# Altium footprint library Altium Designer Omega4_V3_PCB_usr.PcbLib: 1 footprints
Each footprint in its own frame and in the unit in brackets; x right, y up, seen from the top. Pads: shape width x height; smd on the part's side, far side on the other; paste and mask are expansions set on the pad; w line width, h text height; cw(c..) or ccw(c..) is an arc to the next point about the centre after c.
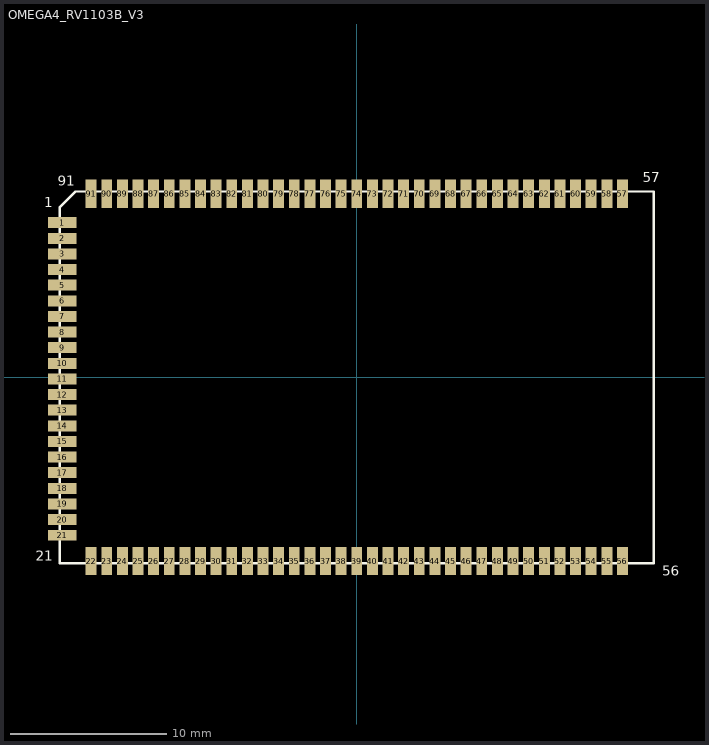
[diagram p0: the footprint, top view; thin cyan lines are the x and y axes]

## OMEGA4_RV1103B_V3 [mm]
pads (91):
  rect 1.8x0.7 smd: 1(-18.85,9.9) 2(-18.85,8.9) 3(-18.85,7.9) 4(-18.85,6.9) 5(-18.85,5.9) 6(-18.85,4.9) 7(-18.85,3.9) 8(-18.85,2.9) 9(-18.85,1.9) 10(-18.85,0.9) 11(-18.85,-0.1) 12(-18.85,-1.1) 13(-18.85,-2.1) 14(-18.85,-3.1) 15(-18.85,-4.1) 16(-18.85,-5.1) 17(-18.85,-6.1) 18(-18.85,-7.1) 19(-18.85,-8.1) 20(-18.85,-9.1) 21(-18.85,-10.1)
  rect 0.7x1.8 smd: 22(-17,-11.75) 23(-16,-11.75) 24(-15,-11.75) 25(-14,-11.75) 26(-13,-11.75) 27(-12,-11.75) 28(-11,-11.75) 29(-10,-11.75) 30(-9,-11.75) 31(-8,-11.75) 32(-7,-11.75) 33(-6,-11.75) 34(-5,-11.75) 35(-4,-11.75) 36(-3,-11.75) 37(-2,-11.75) 38(-1,-11.75) 39(0,-11.75) 40(1,-11.75) 41(2,-11.75) 42(3,-11.75) 43(4,-11.75) 44(5,-11.75) 45(6,-11.75) 46(7,-11.75) 47(8,-11.75) 48(9,-11.75) 49(10,-11.75) 50(11,-11.75) 51(12,-11.75) 52(13,-11.75) 53(14,-11.75) 54(15,-11.75) 55(16,-11.75) 56(17,-11.75) 57(17,11.75) 58(16,11.75) 59(15,11.75) 60(14,11.75) 61(13,11.75) 62(12,11.75) 63(11,11.75) 64(10,11.75) 65(9,11.75) 66(8,11.75) 67(7,11.75) 68(6,11.75) 69(5,11.75) 70(4,11.75) 71(3,11.75) 72(2,11.75) 73(1,11.75) 74(0,11.75) 75(-1,11.75) 76(-2,11.75) 77(-3,11.75) 78(-4,11.75) 79(-5,11.75) 80(-6,11.75) 81(-7,11.75) 82(-8,11.75) 83(-9,11.75) 84(-10,11.75) 85(-11,11.75) 86(-12,11.75) 87(-13,11.75) 88(-14,11.75) 89(-15,11.75) 90(-16,11.75) 91(-17,11.75)
L26-Silk Screen Top (Multiple PADS layers...):
  lines w0.15: -19,-11.9 -19,10.9 -18,11.9 19,11.9 19,-11.9 -19,-11.9
  text "1" at -20,10.9 h0.64
  text "91" at -19.15,12.25 h0.64
  text "21" at -20.54,-11.722 h0.64
  text "56" at 19.55,-12.7 h0.64
  text "57" at 18.3,12.5 h0.64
